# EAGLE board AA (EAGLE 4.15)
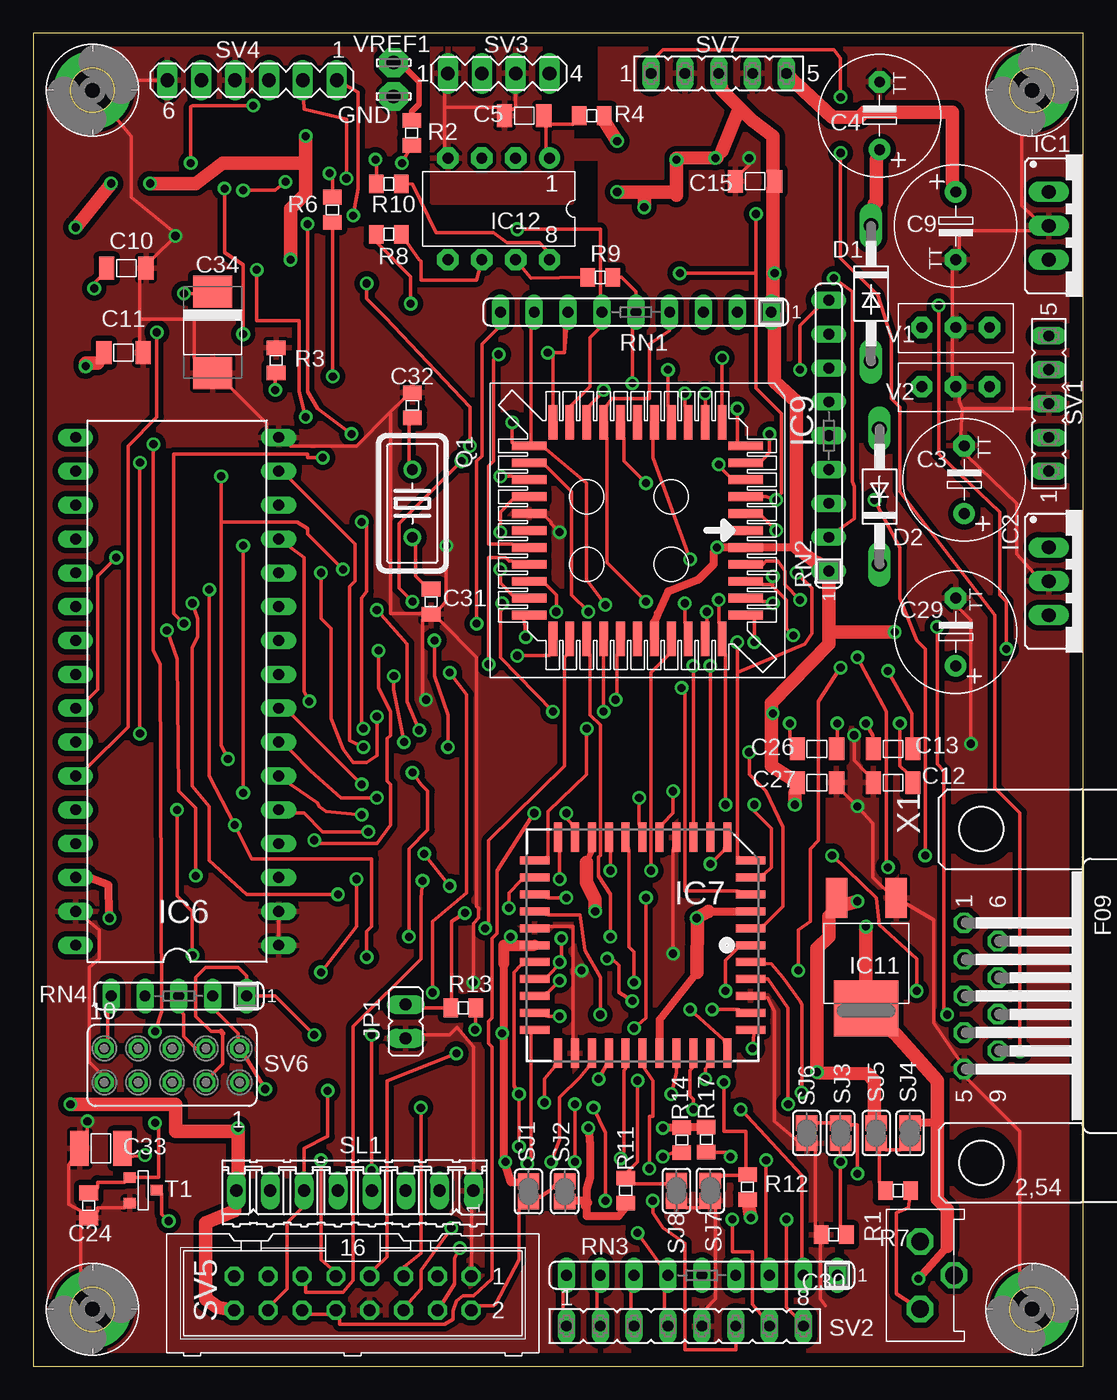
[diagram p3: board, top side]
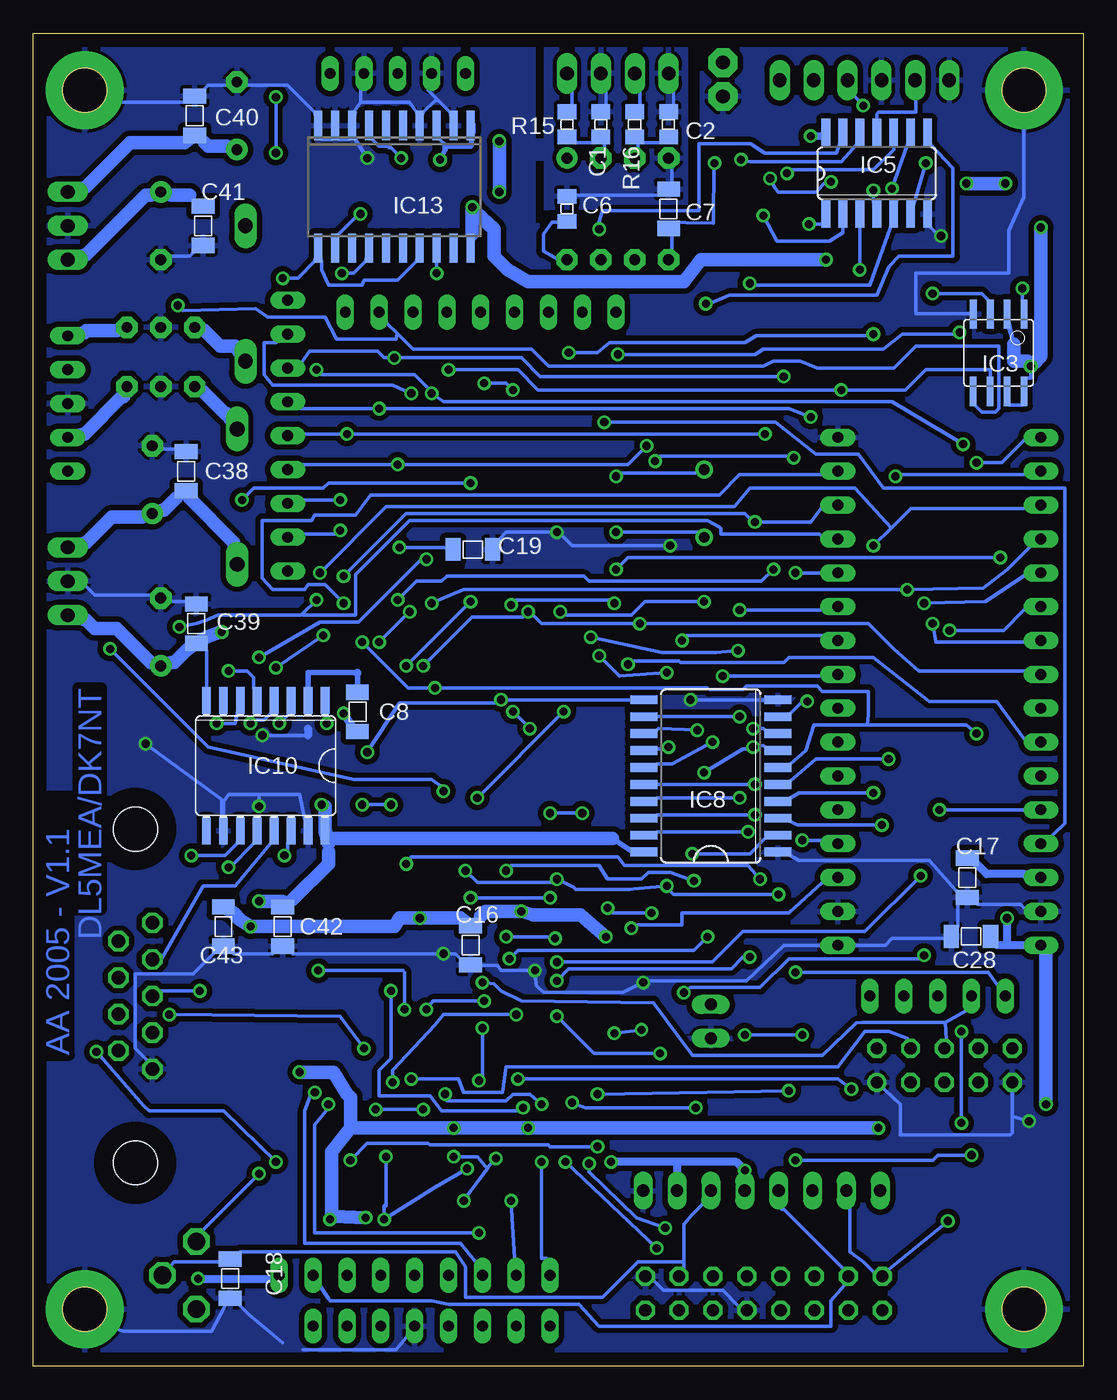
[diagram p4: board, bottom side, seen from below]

Size 78.77 x 100 mm. Coordinates in mm from the lower left corner, seen from the top.
Outline: 0,0 78.77,0 78.77,100 0,100 0,0
Copper layers (1*16): Top 0.035mm / dielectric 1.5mm / Bottom 0.035mm
Design rules "default": minimum track width 10mil, minimum drill 24mil, track to track 8mil, track to pad 8mil, pad to pad 8mil, via to via 8mil, smd to smd 8mil, copper to edge 40mil, drill to drill 8mil, minimum pad ring 10mil, minimum via ring 8mil, stop-mask expansion 4mil, vias tented up to drill 0mil, thermal gap 10mil

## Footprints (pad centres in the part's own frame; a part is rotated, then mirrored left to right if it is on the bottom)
0805 = smd 1.092 x 1.397: 1 -0.94,0; 2 0.94,0
TT5D9 = drill 0.813 pad 1.6 round: + 2.54,0 | drill 0.813 pad 1.6 octagon: - -2.54,0
C1206 = smd 1.143 x 1.702: 1 -1.473,0; 2 1.473,0
1210 = smd 1.397 x 2.591: 1 -1.6,0; 2 1.6,0
CT7243 = smd 2.388 x 2.896: 1 -3.048,0; 2 3.048,0
DO41-10 = drill 1.118 long: A 5.08,0; C -5.08,0
LSP10 = drill 1.016 pad 2.159 octagon: MP 0,0
78XXS = drill 1.016 long: GND 0,-2.54; IN -2.54,-2.54; OUT 2.54,-2.54
SOP-08 = smd 0.5 x 2.2: 1 -1.905,-2.9; 2 -0.645,-2.9; 3 0.625,-2.9; 4 1.895,-2.9; 5 1.905,2.9; 6 0.635,2.9; 7 -0.635,2.9; 8 -1.905,2.9
SO14 = smd 0.66 x 2.032: 1 -3.81,-3.073; 2 -2.54,-3.073; 3 -1.27,-3.073; 4 0,-3.073; 5 1.27,-3.073; 6 2.54,-3.073; 7 3.81,-3.073; 8 3.81,3.073; 9 2.54,3.073; 10 1.27,3.073; 11 0,3.073; 12 -1.27,3.073; 13 -2.54,3.073; 14 -3.81,3.073
DIL32 = drill 0.813 long: 1 -19.05,-7.62; 2 -16.51,-7.62; 3 -13.97,-7.62; 4 -11.43,-7.62; 5 -8.89,-7.62; 6 -6.35,-7.62; 7 -3.81,-7.62; 8 -1.27,-7.62; 9 1.27,-7.62; 10 3.81,-7.62; 11 6.35,-7.62; 12 8.89,-7.62; 13 11.43,-7.62; 14 13.97,-7.62; 15 16.51,-7.62; 16 19.05,-7.62; 17 19.05,7.62; 18 16.51,7.62; 19 13.97,7.62; 20 11.43,7.62; 21 8.89,7.62; 22 6.35,7.62; 23 3.81,7.62; 24 1.27,7.62; 25 -1.27,7.62; 26 -3.81,7.62; 27 -6.35,7.62; 28 -8.89,7.62; 29 -11.43,7.62; 30 -13.97,7.62; 31 -16.51,7.62; 32 -19.05,7.62
PLCC44 = smd 0.6 x 2.2: 1 0,8.1; 2 -1.27,8.1; 3 -2.54,8.1; 4 -3.81,8.1; 5 -5.08,8.1; 6 -6.35,8.1; 18 -6.35,-8.1; 19 -5.08,-8.1; 20 -3.81,-8.1; 21 -2.54,-8.1; 22 -1.27,-8.1; 23 0,-8.1; 24 1.27,-8.1; 25 2.54,-8.1; 26 3.81,-8.1; 27 5.08,-8.1; 28 6.35,-8.1; 40 6.35,8.1; 41 5.08,8.1; 42 3.81,8.1; 43 2.54,8.1; 44 1.27,8.1 | smd 2.2 x 0.6: 7 -8.1,6.35; 8 -8.1,5.08; 9 -8.1,3.81; 10 -8.1,2.54; 11 -8.1,1.27; 12 -8.1,0; 13 -8.1,-1.27; 14 -8.1,-2.54; 15 -8.1,-3.81; 16 -8.1,-5.08; 17 -8.1,-6.35; 29 8.1,-6.35; 30 8.1,-5.08; 31 8.1,-3.81; 32 8.1,-2.54; 33 8.1,-1.27; 34 8.1,0; 35 8.1,1.27; 36 8.1,2.54; 37 8.1,3.81; 38 8.1,5.08; 39 8.1,6.35
SO20W = smd 0.66 x 2.032: 1 -5.715,-5.029; 2 -4.445,-5.029; 3 -3.175,-5.029; 4 -1.905,-5.029; 5 -0.635,-5.029; 6 0.635,-5.029; 7 1.905,-5.029; 8 3.175,-5.029; 9 4.445,-5.029; 10 5.715,-5.029; 11 5.715,5.029; 12 4.445,5.029; 13 3.175,5.029; 14 1.905,5.029; 15 0.635,5.029; 16 -0.635,5.029; 17 -1.905,5.029; 18 -3.175,5.029; 19 -4.445,5.029; 20 -5.715,5.029
PLCC44SO = smd 0.66 x 2.591: 1 0,8.128; 2 -1.27,8.128; 3 -2.54,8.128; 4 -3.81,8.128; 5 -5.08,8.128; 6 -6.35,8.128; 18 -6.35,-8.128; 19 -5.08,-8.128; 20 -3.81,-8.128; 21 -2.54,-8.128; 22 -1.27,-8.128; 23 0,-8.128; 24 1.27,-8.128; 25 2.54,-8.128; 26 3.81,-8.128; 27 5.08,-8.128; 28 6.35,-8.128; 40 6.35,8.128; 41 5.08,8.128; 42 3.81,8.128; 43 2.54,8.128; 44 1.27,8.128 | smd 2.591 x 0.66: 7 -8.128,6.35; 8 -8.128,5.08; 9 -8.128,3.81; 10 -8.128,2.54; 11 -8.128,1.27; 12 -8.128,0; 13 -8.128,-1.27; 14 -8.128,-2.54; 15 -8.128,-3.81; 16 -8.128,-5.08; 17 -8.128,-6.35; 29 8.128,-6.35; 30 8.128,-5.08; 31 8.128,-3.81; 32 8.128,-2.54; 33 8.128,-1.27; 34 8.128,0; 35 8.128,1.27; 36 8.128,2.54; 37 8.128,3.81; 38 8.128,5.08; 39 8.128,6.35
SO16L = smd 0.66 x 2.032: 1 -4.445,-4.902; 2 -3.175,-4.902; 3 -1.905,-4.902; 4 -0.635,-4.902; 5 0.635,-4.902; 6 1.905,-4.902; 7 3.175,-4.902; 8 4.445,-4.902; 9 4.445,4.902; 10 3.175,4.902; 11 1.905,4.902; 12 0.635,4.902; 13 -0.635,4.902; 14 -1.905,4.902; 15 -3.175,4.902; 16 -4.445,4.902
DPAK = smd 1.6 x 2.997: 1 -3.531,-3.658; 3 0.94,-3.658 | smd 4.826 x 4.191: 4 -1.27,4.623
DIL08 = drill 0.813 pad 1.6 round: 1 -6.35,-2.54 | drill 0.813 pad 1.6 octagon: 2 -3.81,-2.54; 3 -1.27,-2.54; 4 1.27,-2.54; 5 1.27,5.08; 6 -1.27,5.08; 7 -3.81,5.08; 8 -6.35,5.08
SO20W' = smd 0.6 x 2.2: 1 -5.715,-4.6; 2 -4.445,-4.6; 3 -3.175,-4.6; 4 -1.905,-4.6; 5 -0.635,-4.6; 6 0.635,-4.6; 7 1.905,-4.6; 8 3.175,-4.6; 9 4.445,-4.6; 10 5.715,-4.6; 11 5.715,4.6; 12 4.445,4.6; 13 3.175,4.6; 14 1.905,4.6; 15 0.635,4.6; 16 -0.635,4.6; 17 -1.905,4.6; 18 -3.175,4.6; 19 -4.445,4.6; 20 -5.715,4.6
JP1 = drill 0.914 long: 1 0,-1.27; 2 0,1.27
BO3,3-PS = drill 3.302 pad 5.842 round: B3,3 0,0
HC18U-V = drill 0.813 round: 1 -2.54,0; 2 2.54,0
ECP10P = drill 1.321 octagon: 1 -2.54,0; 2 0,2.54; 3 2.54,0
SIL9 = drill 0.813 long: 1 -10.16,0; 2 -7.62,0; 3 -5.08,0; 4 -2.54,0; 5 0,0; 6 2.54,0; 7 5.08,0; 8 7.62,0; 9 10.16,0
SIL5 = drill 0.813 long: 1 -5.08,0; 2 -2.54,0; 3 0,0; 4 2.54,0; 5 5.08,0
SJ = smd 1.168 x 1.6: 1 -0.762,0; 2 0.762,0
08P = drill 0.914 long: 1 -8.89,0; 2 -6.35,0; 3 -3.81,0; 4 -1.27,0; 5 1.27,0; 6 3.81,0; 7 6.35,0; 8 8.89,0
FE05-1 = drill 0.813 long: 1 -5.08,0; 2 -2.54,0; 3 0,0; 4 2.54,0; 5 5.08,0
FE08 = drill 0.813 long: 1 -8.89,0; 2 -6.35,0; 3 -3.81,0; 4 -1.27,0; 5 1.27,0; 6 3.81,0; 7 6.35,0; 8 8.89,0
MA04-1 = drill 1.016 long: 1 -3.81,0; 2 -1.27,0; 3 1.27,0; 4 3.81,0
MA06-1 = drill 1.016 long: 1 -6.35,0; 2 -3.81,0; 3 -1.27,0; 4 1.27,0; 5 3.81,0; 6 6.35,0
ML16 = drill 0.914 octagon: 1 -8.89,-1.27; 2 -8.89,1.27; 3 -6.35,-1.27; 4 -6.35,1.27; 5 -3.81,-1.27; 6 -3.81,1.27; 7 -1.27,-1.27; 8 -1.27,1.27; 9 1.27,-1.27; 10 1.27,1.27; 11 3.81,-1.27; 12 3.81,1.27; 13 6.35,-1.27; 14 6.35,1.27; 15 8.89,-1.27; 16 8.89,1.27
FE05-2 = drill 0.914 round: 1 -5.08,1.27 | drill 0.914 octagon: 2 -5.08,-1.27; 3 -2.54,1.27; 4 -2.54,-1.27; 5 0,1.27; 6 0,-1.27; 7 2.54,1.27; 8 2.54,-1.27; 9 5.08,1.27; 10 5.08,-1.27
SOT-23 = smd 0.787 x 0.889: 1 -0.94,1.016; 2 0.991,1.016; 3 0.025,-1.016
EMV1 = drill 0.813 pad 1.6 octagon: 1 -2.54,0; 2 0,0; 3 2.54,0
F09H = drill 1.016 octagon: 1 -5.486,-1.27; 2 -2.743,-1.27; 3 0,-1.27; 4 2.743,-1.27; 5 5.486,-1.27; 6 -4.115,1.27; 7 -1.372,1.27; 8 1.372,1.27; 9 4.115,1.27 | hole 3.302: -12.522,0; 12.522,0

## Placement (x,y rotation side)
C1  100pF  [0805]  36.19,93.18 90 bottom
C2  100pF  [0805]  31.11,93.18 270 bottom
C3  47/25V  [TT5D9]  69.84,66.51 270 top
C4  47/25V  [TT5D9]  63.5,93.81 270 top
C5  100nF  [C1206]  36.83,93.81 180 top
C6  100pF  [0805]  38.73,86.83 90 bottom
C7  100nF  [C1206]  31.11,86.83 270 bottom
C8  1uF  [C1206]  54.45,49.1 270 bottom
C9  47/16V  [TT5D9]  69.21,85.56 90 top
C10  100nF  [C1206]  6.98,82.39 180 top
C11  100nF  [C1206]  6.77,76.04 0 top
C12  1uF  [C1206]  64.51,43.78 180 top
C13  1uF  [C1206]  64.51,46.32 0 top
C15  100nF  [C1206]  54.16,88.89 180 top
C16  100nF  [C1206]  45.97,31.58 270 bottom
C17  100nF  [C1206]  8.69,36.64 270 bottom
C18  100nF  [C1206]  64,6.57 270 bottom
C19  100nF  [C1206]  45.8,61.28 0 bottom
C24  1nF  [0805]  4.16,12.07 270 top
C26  1uF  [C1206]  58.8,46.32 0 top
C27  1uF  [C1206]  58.8,43.78 0 top
C28  100nF  [C1206]  8.42,32.24 180 bottom
C29  47/16V  [TT5D9]  69.21,55.08 270 top
C30  10nF  [0805]  60.07,9.87 180 top
C31  12pF  [0805]  29.84,57.37 270 top
C32  12pF  [0805]  28.44,72.1 90 top
C33  4.7uF/10V  [1210]  5.08,16.34 180 top
C34  10uF/16V  [CT7243]  13.46,77.56 270 top
C38  100nF  [C1206]  67.3,67.14 270 bottom
C39  100nF  [C1206]  66.54,55.71 270 bottom
C40  100nF  [C1206]  66.67,93.81 270 bottom
C41  100nF  [C1206]  66.03,85.56 90 bottom
C42  100nF  [C1206]  60.07,32.98 90 bottom
C43  100nF  [C1206]  64.51,32.98 90 bottom
D1  1N4004  [DO41-10]  62.86,80.48 270 top
D2  1N4004  [DO41-10]  63.5,65.24 90 top
GND  LSP10  [LSP10]  27.03,95.27 0 top
IC1  78M12  [78XXS]  78.73,85.56 270 top
IC2  78M05  [78XXS]  78.73,58.89 270 top
IC3  TL7705SO  [SOP-08]  6.34,76.03 180 bottom
IC5  74HC04D  [SO14]  15.49,89.5 0 bottom
IC6  8K*8/128K*8 SRAM  [DIL32]  10.79,50.63 90 top
IC7  XCR3064PLCC44  [PLCC44]  45.72,31.58 270 top
IC8  74HCT573D  [SO20W]  27.93,44.28 90 bottom
IC9  89C51RD2  [PLCC44SO]  45.33,62.7 270 top
IC10  MAX232AECWE  [SO16L]  61.34,45.05 180 bottom
IC11  MC33269  [DPAK]  61.21,31.46 180 top
IC12  MAX157  [DIL08]  32.38,88.1 180 top
IC13  FM24C256  [SO20W']  51.68,88.48 180 bottom
JP1  [JP1]  27.93,25.87 0 top
PAD1  BO3,3PS  [BO3,3-PS]  4.44,95.72 0 top
PAD2  BO3,3PS  [BO3,3-PS]  74.92,95.72 0 top
PAD3  BO3,3PS  [BO3,3-PS]  74.92,4.28 0 top
PAD4  BO3,3PS  [BO3,3-PS]  4.44,4.28 0 top
Q1  11.052MHz  [HC18U-V]  28.44,64.73 270 top
R1  10K  [ECP10P]  66.54,6.82 270 top
R2  47  [0805]  28.39,92.53 90 top
R3  4.7K  [0805]  18.22,75.46 90 top
R4  10  [0805]  41.91,93.81 0 top
R6  10  [0805]  22.44,86.77 90 top
R7  10K  [0805]  64.89,13.17 180 top
R8  47  [0805]  26.66,84.92 180 top
R9  47  [0805]  42.54,81.69 0 top
R10  47  [0805]  26.66,88.7 180 top
R11  4.7K  [0805]  44.45,13.17 270 top
R12  4.7K  [0805]  53.59,13.42 270 top
R13  4.7K  [0805]  32.25,26.89 0 top
R14  4.7K  [0805]  48.66,16.96 270 top
R15  22  [0805]  38.73,93.18 270 bottom
R16  22  [0805]  33.65,93.18 270 bottom
R17  4.7K  [0805]  50.5,17 270 top
RN1  4.7K  [SIL9]  45.21,79.08 180 top
RN2  4.7K  [SIL9]  59.69,69.81 90 top
RN3  4.7K  [SIL9]  50.16,6.82 180 top
RN4  4,7K  [SIL5]  10.92,27.77 180 top
SJ1  [SJ]  37.16,13.11 90 top
SJ2  [SJ]  39.88,13.11 90 top
SJ3  [SJ]  60.57,17.49 90 top
SJ4  [SJ]  65.78,17.49 90 top
SJ5  [SJ]  63.24,17.49 90 top
SJ6  [SJ]  58.03,17.49 90 top
SJ7  [SJ]  50.8,13.17 270 top
SJ8  [SJ]  48.26,13.17 270 top
SL1  [08P]  24.12,13.17 180 top
SV1  [FE05-1]  76.19,72.22 90 top
SV2  [FE08]  48.89,3.01 0 top
SV3  [MA04-1]  34.92,96.99 0 top
SV4  [MA06-1]  16.41,96.48 180 top
SV5  [ML16]  23.97,5.47 180 top
SV6  Pfosten2*5  [FE05-2]  10.41,22.57 180 top
SV7  [FE05-1]  51.43,96.99 0 top
T1  FDN335N  [SOT-23]  8.25,13.17 90 top
V1  DSS306  [EMV1]  69.21,77.94 180 top
V2  DSS306  [EMV1]  69.21,73.5 180 top
VREF1  LSP10  [LSP10]  27.03,97.8 0 top
X1  [F09H]  71.11,27.77 270 top

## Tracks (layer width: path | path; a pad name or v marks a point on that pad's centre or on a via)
+3V  (via drill 0.6, 0.61)
  Top 0.254: 35.3,15.33 35.36,15.27 v35.43,15.33 | 46.98,24.73 IC7.35 | 41.91,38.7 IC7.15 | v49.78,33.62 50.41,34.12 49.84,33.68 | 35.81,31.84 v35.81,32.22 | 13.06,21.53 14.22,22.7 14.22,24.98 | 14.09,25.11 13.33,25.11 12.19,26.25 12.19,29.17 12.95,29.93 15.36,29.93 16,29.3 RN4.1 18.16,27.77 v21.08,24.85 | R13.2 33.19,25.29 v33.14,25.23 | 35.3,24.73 v35.17,24.98 | v25.39,24.85 v25.39,14.69
  Top 0.406: 41.52,37.81 41.91,38.7 | 12.82,20.92 13.08,21.17 SV6.3 13.06,21.3 13.06,21.53 | 14.22,24.98 14.09,25.11
  Top 0.61: 35.36,15.27 35.81,13.81 SJ1.2 | 35.3,15.33 35.3,24.73 35.3,30.19 | 68.57,8.98 v66.42,6.57 | 67.81,18.25 SJ4.2 | 46.98,24.73 46.98,26 49.78,29.55 | 50.67,34.12 IC7.3
  Top 0.813: 35.3,30.19 35.3,31.58 35.94,31.58 | 35.94,31.58 35.81,31.84 | 35.94,31.58 IC7.23
  Top 1.016: 68.57,8.98 68.57,11.77 67.81,12.54 67.81,18.25 67.81,21.42 64.77,24.85 IC11.4 v62.48,32.98 | 50.67,34.12 49.84,33.68 49.78,29.55 | v42.16,34.12 42.16,35.01 41.52,36.28 41.52,37.81
  Bottom 0.254: 45.21,33.74 45.21,33.49 C16.1 | v35.17,24.98 v33.14,25.23 | v21.08,24.85 v25.39,24.85
  Bottom 0.61: 30.47,15.33 26.03,15.33 v25.39,14.69 SL1.4 | 30.47,15.33 v35.43,15.33 | 30.47,15.33 SL1.2 | v66.42,6.57 60.57,6.57 RN3.1
  Bottom 1.016: C16.1 46.73,33.62 v49.78,33.62 51.3,33.62 51.68,32.98 v62.48,32.98 63.24,33.49 63.75,34 C43.2 | 45.21,33.74 44.83,34.12 v42.16,34.12 41.27,33.87 37.71,33.87 v35.81,32.22
+5V  (via drill 0.6, 0.61)
  Top 0.254: 3.93,75.27 v3.93,75.02 3.68,74.64 | 4.82,75.27 C11.1 | v5.71,33.62 5.71,33.87 | 41.52,11.27 41.39,12.02 | 44.45,11.9 R11.2 | 10.66,17.61 13.97,17.36 15.62,17.61 | SL1.8 15.22,13.27 15.24,17.61 | 59.69,33.74 IC11.3 60.96,34.63 | v51.3,61.43 51.05,61.05 | 58.8,60.29 59.05,60.03 | 42.92,93.31 R4.2 | 55.49,88.35 C15.1 55.49,89.62 | RN1.1 55.49,79.34 | 55.49,82.26 v55.62,82 | 53.08,94.32 52.95,94.32 | 57.15,43.02 C27.1 | 51.68,91.15 51.29,90.68 49.38,90.53 49.4,90.51 49.53,90.64 v51.18,90.64 | SV2.8 57.78,3.14 56.51,4.41 v56.51,11.01 | v47.24,17.87 47.37,17.9 | R14.1 48.76,17.9 48.76,17.94
  Top 0.406: v48.26,90.51 48.38,90.51 | 47.87,88.1 47.93,88.1 47.93,87.85 48.26,87.85
  Top 0.61: 5.71,33.87 5.65,36.09 4.19,36.66 IC6.30 | 41.52,12.41 41.52,11.27 43.94,11.27 44.45,11.9 | 41.52,12.41 40.76,12.41 SJ2.1 | v51.3,61.43 IC9.44 57.27,61.43 | 51.05,61.05 51.05,60.16 49.91,59.02 47.62,58.13 46.86,56.48 46.6,55.84 IC9.35 | v41.65,17.87 41.78,16.6 41.78,14.19 41.52,13.3 41.52,12.41 | 41.39,12.02 41.65,12.28 41.52,12.41 | 55.37,46.19 55.24,46.19 v55.49,48.98 | 47.37,17.9 R14.1 | 48.76,17.94 R17.1
  Top 1.016: 3.93,75.27 4.82,75.27 | SL1.8 15.11,11.65 12.95,10.76 12.95,5.04 13.84,4.41 SV5.16 15.11,4.28 | 15.24,17.61 10.66,17.61 10.66,19.65 v2.79,19.65 | 59.69,33.74 59.69,32.22 58.8,31.33 v58.8,22.06 58.86,22 62.61,21.93 63.11,21.42 63.11,18.76 SJ5.2 | 60.96,34.63 v61.84,34.89 | C27.1 55.37,45.05 55.37,46.19 55.37,49.75 59.69,54.19 59.69,55.08 | 59.05,60.03 57.27,61.43 57.27,72.35 55.62,73.88 55.62,78.83 RN1.1 | 58.8,60.29 RN2.1 59.69,55.08 | 59.69,55.08 v64.64,55.08 | 47.87,88.1 45.84,88.1 | 45.84,88.1 v43.81,88.1 | v43.81,91.91 42.92,93.31 | 55.49,79.34 55.49,82.26 55.49,88.35 | 55.49,89.62 55.49,92.29 53.91,93.5 53.08,94.32 51.68,95.72 SV7.3 | 52.95,94.32 51.68,91.15 | 48.26,87.85 v48.26,90.51 48.26,90.64 51.29,90.68 | v19.3,83.02 19.3,86.83 20.44,87.97 20.44,90.26 | 20.44,90.26 v20.44,92.29 | v57.15,42.13 57.15,43.02 | v5.84,88.73 v3.17,85.43 | v8.76,88.73 12.19,88.73 14.22,90.26 20.44,90.26 | 45.84,88.1 v45.84,86.96 | v53.84,11.14 R12.2 | 15.22,13.27 15.34,13.27 15.36,13.3 v15.36,17.87
  Bottom 0.254: IC3.7 5.58,72.1 4.57,72.1 IC3.8 4.31,74.13 3.93,74.13 v3.93,75.02 4.19,75.4 4.06,75.27 3.68,75.27 | 59.3,35.01 C42.2 60.07,34.89 | 56.64,38.57 56.64,39.2 56.64,39.46 56.76,39.59 | 68.45,52.79 C29.+ | IC10.8 65.78,53.68 C39.2 | v51.3,61.43 47.75,61.43 C19.1 | v64.64,55.08 64.77,55.08 | v55.62,82 54.73,82 53.84,82.89 IC13.14 | 45.72,92.55 45.72,93.18 IC13.1 | 19.43,83.02 v19.3,83.02 | 45.84,84.92 IC13.20 | IC13.1 45.84,92.16 45.84,91.53 45.97,91.53 | 47.81,91.59 47.75,91.53 45.97,91.53 | 47.81,91.59 48.26,92.04 IC13.3 | 52.83,91.53 53.34,92.04 IC13.7 53.59,92.29 52.83,91.53 | 47.87,91.53 47.81,91.59 | 45.97,91.53 IC13.1 | 52.83,91.53 52.19,91.53 52.07,91.4 51.94,91.4 v51.18,90.64 | 19.58,92.32 IC5.14 | 56.26,11.26 56.26,11.27 | 56.26,11.25 56.26,11.26 | 56.26,11.26 v56.51,11.01 | 5.2,76.67 IC3.2 5.7,78.33 5.71,78.32 5.71,78.19 5.2,76.67
  Bottom 0.406: 35.3,39.59 33.78,38.57 IC8.20 | v48.26,90.51 47.87,91.28 47.87,91.53 45.97,91.53 | v45.84,86.96 45.97,86.96 45.59,86.58
  Bottom 0.61: 5.71,31.58 6.47,31.58 C28.1 | IC6.32 5.71,31.58 | C17.1 7.87,37.55 7.23,36.92 4.44,36.92 IC6.30 | 5.71,31.58 v5.71,33.62 | v20.44,92.29 19.58,92.32 | C8.2 54.45,47.36 v55.49,48.98
  Bottom 1.016: v2.79,19.65 2.79,31.08 IC6.32 | 59.3,35.01 56.64,37.68 56.64,38.57 | 56.64,39.2 IC10.16 56.89,42 v57.15,42.13 | 56.76,39.59 35.3,39.59 | v61.84,34.89 60.07,34.89 | 68.45,52.79 68.19,52.79 67.3,53.68 C39.2 65.78,54.7 64.77,55.08 | IC2.OUT 74.8,55.97 74.16,55.33 72.51,55.33 69.97,52.79 C29.+ | v43.81,88.1 v43.81,91.91 | 19.43,83.02 28.7,83.02 29.97,81.37 41.65,81.37 43.18,82.26 44.19,83.27 44.19,85.31 45.59,86.58 | 54.99,17.87 56.38,16.09 56.38,11.27 56.26,11.25 v53.84,11.14 | 54.99,17.87 54.99,20.15 55.24,20.41 56.26,22.06 v58.8,22.06 | 5.2,76.67 5.2,75.4 4.19,75.4 | 3.68,75.27 3.17,75.78 v3.17,85.43 | v8.76,88.73 v5.84,88.73 | v45.84,86.96 45.84,84.92 | 54.99,17.87 v47.24,17.87 v41.65,17.87 v15.36,17.87
+12V
  Top 1.016: C9.+ 68.96,88.86 68.96,94.07 62.35,94.07 61.97,93.69 59.94,93.69 57.27,96.23 SV7.5
  Bottom 0.254: 67.05,87.85 66.8,87.59 C41.2 | C9.+ 69.97,87.85
  Bottom 1.016: 67.05,87.85 68.45,87.85 C9.+ | 69.97,87.85 70.35,87.85 74.8,83.4 IC1.OUT
-V  (via drill 0.61)
  Top 0.254: C30.1 60.57,10.5 v60.57,15.33 SJ3.1 | 60.57,91.15 v60.57,91.02 60.57,83.15 63.37,80.35 64.38,77.18 64.38,72.61 65.02,71.97 65.02,65.62 72.13,56.35 72.13,43.4 74.04,41.49 v74.04,23.58 | v60.57,95.21 60.57,98.13 60.07,98.77 47.24,98.77 46.35,97.88 SV7.1
  Bottom 0.254: v60.57,91.02 v60.57,95.21 | v74.04,23.58 70.48,19.52 70.1,19.14 64.51,19.14 v60.57,15.33
A00  (via drill 0.61)
  Top 0.254: v25.78,48.73 25.78,45.81 25.01,45.3 24,45.3 23.24,46.32 22.35,48.6 22.35,55.33 21.58,56.1 v21.58,59.52
  Bottom 0.254: v21.58,59.52 21.46,59.4 21.2,59.52 IC6.12 18.28,59.65 | v25.78,48.73 IC8.12
A01  (via drill 0.61)
  Top 0.254: v28.95,47.71 28.06,49.87 28.06,54.19 v25.78,56.73
  Bottom 0.254: v28.95,47.71 31.87,47.84 32,47.71 IC8.13 | v25.78,56.73 19.68,56.73 IC6.11
A02  (via drill 0.61)
  Top 0.254: v31.11,46.44 31.11,48.86 30.09,51.78 v30.09,54.45
  Bottom 0.254: v31.11,46.44 31.24,46.32 31.87,46.32 IC8.14 | v30.09,54.45 29.71,54.83 19.55,54.83 IC6.10
A03  (via drill 0.61)
  Top 0.254: v27.81,46.82 27.05,50.76 v27.05,51.78
  Bottom 0.254: v27.81,46.82 30.86,45.17 32,45.17 IC8.15 | v27.05,51.78 19.68,51.78 IC6.9
A04  (via drill 0.61)
  Top 0.254: v24.63,43.65 19.43,48.86 IC6.8
  Bottom 0.254: v24.63,43.65 IC8.16
A05  (via drill 0.61)
  Top 0.254: v25.78,42.63 23.11,42.63 20.82,44.67 19.3,46.19 IC6.7
  Bottom 0.254: v25.78,42.63 32,42.63 IC8.17
A06  (via drill 0.61)
  Top 0.254: v24.63,41.36 21.97,41.62 21.46,42 21.33,42.25 19.3,43.65 IC6.6
  Bottom 0.254: v24.63,41.36 32,41.36 IC8.18
A07  (via drill 0.61)
  Top 0.254: v25.14,40.09 21.71,40.09 20.31,41.49 19.68,41.49 IC6.5
  Bottom 0.254: v25.14,40.09 32,40.09 IC8.19
A08  (via drill 0.61)
  Top 0.254: v34.92,75.91 34.54,75.53 34.54,67.91 34.16,67.53 34.16,61.68 35.94,61.68 IC9.24 | v9.27,77.56 9.27,71.21 7.11,69.05 7.11,47.97 4.06,44.92 IC6.27
  Bottom 0.254: v34.92,75.91 24.63,75.91 24,76.29 14.98,76.29 13.58,77.43 9.39,77.43 v9.27,77.56
A09  (via drill 0.61)
  Top 0.254: v34.16,52.67 34.16,60.67 35.43,60.67 35.68,60.41 35.94,60.41 IC9.25
  Bottom 0.254: v34.16,52.67 33.9,52.92 30.35,52.92 30.22,52.79 22.47,52.79 22.09,53.17 15.74,53.17 11.55,49.87 6.47,49.87 4.44,47.08 IC6.26
A10  (via drill 0.61)
  Top 0.254: v39.24,56.6 39.24,57.87 38.48,58.64 IC9.26 | v28.44,57.37 27.43,58.38 27.43,63.21 v32.13,67.91 | v21.71,68.16 20.57,68.16 20.57,68.41 10.54,68.41 10.54,56.48 v11.3,55.71
  Bottom 0.254: v39.24,56.6 38.98,56.35 33.9,56.35 32.89,57.37 v28.44,57.37 | v32.13,67.91 31.74,68.29 21.84,68.29 v21.71,68.16 | v11.3,55.71 11.04,54.32 4.44,54.32 IC6.23
A11  (via drill 0.61)
  Top 0.254: v35.05,59.78 35.05,58.76 35.94,57.87 IC9.27 | v6.22,60.67 4.82,59.27 4.82,50.76 4.06,50 IC6.25
  Bottom 0.254: v35.05,59.78 34.16,60.67 v6.22,60.67
A12  (via drill 0.61)
  Top 0.254: v36.95,54.7 36.83,56.1 36.7,56.35 IC9.28 | v25.9,53.68 25.9,50.89 26.79,49.11 26.79,47.33 26.54,47.08 26.54,43.9 26.79,43.65 26.79,40.6 25.78,39.2 21.08,39.2 v21.08,39.46
  Bottom 0.254: v36.95,54.7 31.62,53.56 27.55,53.56 v25.9,53.68 | v21.08,39.46 19.68,39.46 IC6.4
A13  (via drill 0.61)
  Top 0.254: v36.32,53.3 38.73,53.3 IC9.29 | v31.24,52.03 32.51,50.38 32.51,35.52 29.97,33.36 v29.97,28.03 | v11.93,30.82 11.93,34.12 10.79,35.27 v10.79,41.74
  Bottom 0.254: v36.32,53.3 34.79,51.78 v31.24,52.03 | v29.97,28.03 29.46,28.41 24.25,28.41 22.09,30.57 11.93,30.57 v11.93,30.82 | v10.79,41.74 IC6.28
A14  (via drill 0.61)
  Top 0.254: v33.9,32.85 34.16,33.36 34.16,39.46 39.87,45.05 39.87,53.17 40,53.3 IC9.30
  Bottom 0.254: v33.9,32.85 33.65,33.11 30.09,33.11 30.09,34 22.09,34 19.17,36.66 IC6.3
AD0  (via drill 0.61)
  Top 0.254: v20.7,49.87 20.31,50.63 20.31,60.67 19.3,61.43 IC6.13 | v53.97,23.84 54.1,25.23 IC7.40 | v67.81,55.46 67.81,45.17 68.32,44.67 68.32,26.38 v68.57,26.38 | v57.53,57.49 56.38,58.64 56.38,59.65 55.88,60.41 54.99,60.41 54.73,60.16 IC9.43
  Bottom 0.254: v20.7,49.87 20.95,50 21.97,48.98 IC8.9 | v53.97,23.84 55.75,26.25 v68.57,26.38 | v67.81,55.46 66.54,55.71 65.78,55.97 64.89,56.35 58.67,56.35 58.61,56.41 | 58.61,56.41 v57.53,57.49 | IC6.13 19.68,62.32 19.81,62.45 27.17,62.45 27.17,62.83 27.3,62.95 28.19,63.46 50.54,63.46 54.61,59.4 54.61,56.35 58.54,56.35 58.61,56.41
AD1  (via drill 0.61)
  Top 0.254: v24.76,47.84 24.76,48.22 24.63,48.35 24.63,57.62 25.01,58.13 25.01,63.34 v24.63,63.34 | v50.92,26.76 52.83,26.76 IC7.41 | v57.4,29.68 57.4,32.73 58.29,33.36 58.29,38.82 58.92,39.46 58.92,49.87 v60.57,52.41 | v57.02,54.83 56.51,55.33 56.51,57.49 55.43,58.57 | 55.43,58.57 55.37,58.64 54.73,58.64 IC9.42 | v55.49,59.27 55.49,58.64 55.43,58.57
  Bottom 0.254: v24.76,47.84 24,47.84 23.87,47.71 IC8.8 | IC6.14 19.68,64.35 20.44,63.34 v24.63,63.34 25.01,63.59 25.39,63.97 50.8,63.97 v55.49,59.27 | v57.4,29.68 51.05,29.68 50.92,29.55 v50.92,26.76 | v57.02,54.83 v60.57,52.41
AD2  (via drill 0.61)
  Top 0.254: v24.76,46.44 23.74,46.95 23.74,58.51 24.12,58.89 24.12,61.68 19.3,66.51 IC6.15 | v49.27,26.76 51.81,24.47 IC7.39 | v44.95,27.39 43.94,28.03 43.94,30.06 43.43,30.57 v43.05,30.57 | v28.19,32.22 28.19,38.82 29.59,40.22 29.59,43.14 29.08,43.65 v28.44,44.54 | v55.49,57.24 55.49,57.37 54.73,57.37 IC9.41
  Bottom 0.254: IC8.7 23.87,46.44 24,46.57 v24.76,46.44 25.01,46.32 25.52,46.32 v28.44,44.54 | v49.27,26.76 48.76,27.39 v44.95,27.39 | v43.05,30.57 42.41,31.2 29.2,31.2 v28.19,32.22 | v55.49,57.24 56.89,58.64 58.16,58.64 58.41,58.25 60.83,58.25 61.59,59.14 61.59,63.46 57.91,63.46 57.65,63.84 54.61,63.84 53.46,65.37 27.3,65.37 25.78,66.89 19.68,66.89 IC6.15
AD3  (via drill 0.61)
  Top 0.254: v54.1,54.32 54.1,56.1 IC9.40 | v48.64,50.89 48.89,50.63 48.89,35.65 52.83,35.65 IC7.4 | v8,47.46 v8,67.78
  Bottom 0.254: 17.27,48.09 20.19,48.09 20.82,46.19 21.97,45.17 IC8.6 | v54.1,54.32 50.67,50.89 v48.64,50.89 28.19,50.89 28.06,50.76 25.52,50.76 25.27,51.02 19.93,51.02 19.55,50.63 16.12,50.63 16.12,48.86 16.19,48.16 17.27,48.09 | v8,67.78 6.09,67.78 4.44,69.43 IC6.17 | v8,47.46 8.76,48.09 17.27,48.09
AD4  (via drill 0.61)
  Top 0.254: v54.1,42.13 54.1,41.62 55.37,40.35 55.37,37.43 54.86,36.92 IC7.5 | v51.94,42.13 51.94,53.3 IC9.39 51.43,55.84 v51.43,57.49 | v14.6,45.55 14.09,46.57 14.09,63.34 | 14.09,63.34 v14.09,66.76 | v23.24,59.78 20.57,62.45 20.57,62.83 19.81,63.34 14.09,63.34
  Bottom 0.254: v51.94,42.13 v54.1,42.13 | v14.6,45.55 20.06,45.55 21.97,43.9 IC8.5 | v14.09,66.76 13.97,66.89 4.44,66.89 IC6.18 | v51.43,57.49 50.03,58.89 48.13,58.89 47.75,59.27 37.46,59.27 37.08,58.89 24.12,58.89 v23.24,59.78
AD5  (via drill 0.61)
  Top 0.254: 52.83,52.03 v52.83,54.32 | 52.83,52.03 52.83,38.19 IC7.6 | v50.54,56.6 50.54,55.84 IC9.38 | v15.74,43.02 v15.74,61.56 | 52.83,52.03 57.91,54.19 58.41,54.95 58.41,58.38 v57.27,59.52
  Bottom 0.254: v52.83,54.32 v50.54,56.6 | v15.74,43.02 21.33,43.02 21.97,42.63 IC8.4 | 14.41,62.89 12.95,64.35 4.44,64.35 IC6.19 | v15.74,61.56 14.41,62.89 | v57.27,59.52 52.32,64.48 26.16,64.48 25.01,65.88 17.14,65.88 14.41,62.89
AD6  (via drill 0.61)
  Top 0.254: v13.2,58.25 13.2,44.28 v15.11,40.6 16.38,38.06 25.39,38.06 25.39,32.98 25.01,32.6 v25.01,30.7 | v39.49,28.92 38.6,28.03 IC7.26 | v48.89,57.24 48.89,55.84 IC9.37
  Bottom 0.254: v15.11,40.6 21.46,40.6 21.97,40.86 IC8.3 | IC6.20 4.06,61.43 5.71,59.78 7.49,58.38 v13.2,58.25 46.48,58.25 v48.89,57.24 | v39.49,28.92 38.6,29.81 26.41,29.81 25.52,30.7 v25.01,30.7
AD7  (via drill 0.61)
  Top 0.254: v31.24,36.03 v29.33,38.44 | v39.49,36.54 39.49,38.7 IC7.17 | v46.35,37.17 46.35,52.03 47.62,53.3 IC9.36 | v11.93,57.24 12.31,56.1 12.31,54.7 11.93,53.94 11.93,43.52 13.2,42 13.2,37.94 16,35.39 v22.86,35.39
  Bottom 0.254: v29.33,38.44 25.01,38.44 23.87,39.59 IC8.2 | 34.16,35.78 v31.24,36.03 31.24,35.9 30.73,35.39 v22.86,35.39 | 34.16,35.78 34.03,35.78 | 34.16,35.78 38.1,35.78 38.22,35.9 v39.49,36.54 39.87,36.28 45.46,36.28 v46.35,37.17 | v11.93,57.24 7.36,57.37 4.44,59.27 IC6.21
ADCCLK  (via drill 0.61)
  Top 0.254: v36.32,85.31 42.54,85.31 42.54,80.23 RN1.6 42.41,77.81 41.78,77.18 41.78,73.5 40.38,72.1 IC9.16
  Bottom 0.254: v36.32,85.31 36.32,85.81 36.06,86.7 28.82,86.7 28.82,88.86 28.83,91.72 24.99,91.72 23.87,91.02 18.54,91.02 18.28,91.66 IC5.13
ADCCS-  (via drill 0.61)
  Top 0.254: v15.74,77.43 15.74,82.64 14.35,83.53 v14.35,88.35 | v38.6,76.03 38.98,76.03 | 39.87,76.03 RN1.7 39.87,77.81 39.87,76.03 | 38.98,76.03 39.87,76.03 | 38.98,76.03 IC9.17
  Bottom 0.254: v14.35,88.35 13.2,91.66 IC5.9 | v15.74,77.43 16.38,77.3 24.51,77.3 25.39,76.8 35.55,76.8 36.44,76.03 v38.6,76.03
ADCDATA  (via drill 0.61)
  Top 0.254: v42.79,73.24 42.79,73.11 41.78,72.1 IC9.15 | v44.95,73.75 44.95,77.81 RN1.5 45.08,79.08 45.21,79.21 45.21,80.61 44.13,81.69 R9.2
  Bottom 0.254: v42.79,73.24 43.3,73.75 v44.95,73.75
ADR15  (via drill 0.61)
  Top 0.254: 39.55,30.25 39.62,30.31 v39.62,32.09 | 39.55,30.25 38.6,29.3 IC7.25 | v43.3,32.22 43.3,35.39 42.41,36.79 42.41,38.19 42.54,38.32 42.54,48.09 41.78,48.86 41.78,53.3 IC9.31 | v10.03,55.21 10.79,53.05 10.92,43.14 12.19,41.87 v12.19,36.79 | v39.49,30.31 39.55,30.25
  Bottom 0.254: v39.62,32.09 39.75,32.22 v43.3,32.22 | v10.03,55.21 5.96,55.21 4.44,56.73 IC6.22 | v12.19,36.79 16.38,32.6 25.52,32.6 27.81,30.31 v39.49,30.31
ALE  (via drill 0.61)
  Top 0.254: v43.68,50 43.81,50.13 43.81,53.3 IC9.33 | v53.72,46.06 53.72,44.41 54.99,43.14 56.26,40.48 56.26,34.51 54.86,33.11 IC7.2
  Bottom 0.254: IC8.11 v43.68,50 44.06,49.75 51.3,49.75 v53.72,46.06
DREHSTB  (via drill 0.6, 0.61)
  Top 0.254: v46.22,14.82 46.22,18.76 46.48,18.76 46.48,21.42 45.72,22.57 IC7.34 | 52.32,10.88 v52.45,11.01 52.45,8.6 53.97,8.6 53.97,4.66 54.61,3.9 SV2.7 | R17.2 52.32,16.06 v52.32,15.71
  Bottom 0.254: v46.22,14.82 48.64,13.42 v52.45,11.01 52.45,12.03 52.32,12.03 v52.32,15.71
DREHUD  (via drill 0.6, 0.61)
  Top 0.254: v44.06,15.58 44.32,16.09 44.32,22.19 44.45,22.31 IC7.33 | v46.48,12.41 46.48,11.52 47.24,10.38 48.89,9.23 48.89,1.23 52.7,1.23 SV2.6 | R14.2 48.13,16.02 48.13,16.09 v47.24,15.71
  Bottom 0.254: v44.06,15.58 44.45,15.2 46.22,12.79 | v46.48,12.41 46.22,12.79 | 46.22,12.79 44.7,14.82 45.46,15.71 v47.24,15.71
FRAM_SCD  (via drill 0.61)
  Top 0.254: v55.75,62.7 54.73,63.72 IC9.2 | v60.07,81.62 61.46,80.61 61.46,66.38 61.59,66 61.59,63.59 60.57,62.83 RN2.2
  Bottom 0.254: IC13.17 50.03,82.89 51.43,81.5 53.97,81.5 54.1,81.11 56.64,81.11 57.15,82.26 57.15,82.89 IC13.11 57.65,82.89 58.92,81.62 v60.07,81.62 | v55.75,62.7 56,62.45 58.41,62.45 RN2.2
FRAM_SCL  (via drill 0.61)
  Top 0.254: IC9.3 54.99,65.24 v55.75,64.99 56,65.37 56.13,65.49 56.13,71.46 54.22,73.37 54.22,82 | 54.22,82 v54.22,86.45 | 54.22,82 v48.51,82
  Bottom 0.254: v55.75,64.99 58.41,64.99 RN2.3 | 54.29,86.51 55.88,84.92 IC13.12 | 54.29,86.51 54.1,86.7 | v54.22,86.45 54.29,86.51 | v48.51,82 IC13.18
GND  (via drill 0.61)
  Top 0.254: SV4.6 7.23,96.48 PAD1.B3,3 7.36,92.29 7.36,87.72 10.41,85.18 v10.66,84.8 9.01,83.15 C10.1 8,81.62 8,78.58 | 8,78.58 8,76.8 C11.2 | v39.49,62.57 38.86,63.21 38.86,63.34 38.48,63.72 IC9.22 | 26.73,71.53 24.25,69.05 19.3,69.05 IC6.16 17.52,70.32 17.52,70.7 14.85,73.37 C34.2 12.06,75.65 12.06,78.58 8,78.58 | 26.73,71.53 27.81,72.61 C32.2 | C31.2 29.2,56.48 26.79,56.48 26.79,71.46 26.73,71.53 | v29.46,50 29.2,50.13 29.2,55.97 C31.2 | v30.98,61.56 30.98,57.37 30.47,56.86 C31.2 | 69.72,71.84 69.46,72.35 69.46,72.73 V2.2 68.96,74.26 68.96,77.18 V1.2 68.96,78.7 68.96,82.26 C9.- 69.46,83.78 69.46,85.18 74.8,85.18 IC1.GND 75.05,86.19 74.16,87.08 74.16,92.93 PAD2.B3,3 | 69.72,71.84 75.05,71.84 SV1.3 | 69.72,71.84 69.59,69.81 C3.- 70.1,68.29 73.78,64.73 73.78,60.92 75.05,59.52 IC2.GND | v53.72,90.64 53.72,90.13 53.21,89.62 C15.2 | 61.91,41.94 62.99,40.73 62.99,36.66 63.75,35.9 IC11.1 67.56,33.49 67.56,25.74 69.46,22.95 X1.5 70.1,21.55 74.04,17.61 74.04,7.07 PAD3.B3,3 | 61.91,41.94 60.83,43.02 C27.2 | 61.91,41.94 v61.84,42 | SJ8.2 49.02,11.9 50.03,11.9 SJ7.2 51.18,11.9 51.18,5.04 50.41,4.28 SV2.5 | IC7.42 55.11,27.65 55.62,26.63 55.62,18.38 57.27,16.98 SJ6.1 58.67,16.22 58.67,10.5 C30.2 59.05,9.23 59.05,5.04 59.43,4.53 | IC6.1 IC6.2 | v4.06,18.38 4.06,17.61 C33.2 2.66,15.08 2.66,12.15 3.55,11.65 C24.2 | T1.1 6.85,11.9 4.82,11.9 4.82,11.65 C24.2 | C24.2 3.55,10.63 3.55,7.07 PAD4.B3,3 | IC6.31 4.06,33.49 4.95,32.73 4.95,30.57 4.19,29.93 4.19,22.82 5.08,21.93 SV6.9 | 31.81,25.43 31.24,24.85 29.33,24.85 JP1.1 | 31.81,25.43 31.87,25.36 | SV5.1 32.89,7.33 32.89,11.77 SL1.1 33.02,23.96 31.81,25.43
  Top 0.254: 40.51,29.68 40.51,24.47 IC7.30 | 40.51,29.68 40.51,32.98 38.6,32.98 IC7.22 | v48,30.95 48,38.7 IC7.10 | v41.14,29.68 40.51,29.68 | v70.35,46.7 70.35,55.97 69.46,56.86 C29.- | v33.02,28.79 33.02,33.24 33.4,33.62 33.4,34.38 33.27,34.51 33.27,53.17 30.47,55.97 C31.2 | v61.59,47.33 61.59,45.43 62.48,44.54 C12.2
  Bottom 0.254: IC3.4 8.38,78.96 12.57,78.96 12.57,82 5.58,82 5.58,85.18 4.44,87.72 PAD1.B3,3 | SV4.4 15.11,96.38 | v10.66,84.8 10.79,84.8 11.43,85.43 IC5.7 | C19.2 43.81,62.06 43.3,62.57 v39.49,62.57 39.11,62.32 38.35,61.56 v30.98,61.56 | v29.46,50 IC8.10 | C41.1 66.8,83.53 67.05,83.27 68.45,83.27 C9.- | C39.1 67.3,57.37 68.45,57.37 C29.- 69.97,57.87 74.16,57.87 74.8,58.51 IC2.GND | C38.1 68.07,68.8 69.08,68.8 C3.- | 48.45,95.02 49.14,95.72 SV7.2 | 48.45,95.02 47.49,94.07 IC13.2 | 48.45,95.02 48.51,94.96 48.64,94.96 49.53,94.07 IC13.4 50.03,94.07 50.54,94.83 54.22,94.83 | v53.72,90.64 54.61,92.04 IC13.8 | IC13.8 55.11,92.04 55.88,92.04 IC13.9 56.38,92.04 57.15,92.04 IC13.10 57.65,94.07 59.69,96.1 62.73,96.1 C4.- 64.26,96.1 65.65,96.1 65.91,95.85 C40.1 67.43,94.83 72.13,94.83 PAD2.B3,3 | 54.22,94.83 54.73,94.07 54.61,94.07 IC13.8 | 54.22,94.83 54.22,95.72 SV7.4 | 61.84,42.89 64.13,42.89 64.51,42.38 IC10.10 64.64,41.11 64.64,42.51 v70.35,46.7 | 61.84,42.89 58.8,42.89 58.41,41.11 IC10.15 | v61.84,42 61.84,42.89 | 60.07,1.74 62.61,3.9 63.24,4.53 C18.2 64.38,4.53 65.4,2.63 72,2.63 72.89,2.88 PAD3.B3,3 | 58.54,1.23 51.56,1.23 50.8,2.12 SV2.5 | C17.2 9.39,34.63 9.39,32.98 C28.2 10.28,32.09 14.35,32.09 14.85,31.58 IC6.1 22.47,31.58 25.27,28.92 33.02,28.92 v33.02,28.79 34.54,28.03 40.51,28.03 41.02,28.54 41.14,29.3 v41.14,29.68 43.68,29.68 43.94,30.06 45.72,30.06 C16.2 46.73,30.57 47.11,30.95 v48,30.95 59.3,30.95 C42.1 60.83,30.95 63.75,30.95 C43.1 65.27,30.95 66.8,29.43 71.11,29.43 71.11,23.84 70.23,22.95 X1.5 | IC8.1 21.97,38.32 21.33,37.94 11.55,37.94 9.52,35.65 C17.2
  Bottom 0.254: IC6.31 4.44,34.38 4.69,34.63 7.87,34.63 C17.2 | v4.06,18.38 5.33,18.76 SV6.9 5.33,17.49 5.46,17.36 13.71,17.36 13.71,19.65 SV6.1 | SV5.8 25.9,4.53 27.05,5.68 31.49,5.68 32.25,6.44 SV5.1 | 58.16,47.33 v61.59,47.33
  Bottom 0.61: 58.16,47.84 58.16,47.33
  pour Bottom (isolate 0.406): -0.64,99.53 -0.64,0.47 79.37,0.47 79.37,99.53 41.27,99.53 41.27,91.91 40,91.91 40,90.64 41.27,90.64 41.27,85.56 28.57,85.56 28.57,99.53
  pour Top (isolate 0.406): -0.64,99.53 -0.64,0.47 78.1,0.47 78.1,99.53 42.54,99.53 42.54,91.91 40,91.91 40,90.64 42.54,90.64 42.54,85.56 28.57,85.56 28.57,99.53
GNDA
  Top 0.254: SV3.3 36.19,94.45 C5.2 34.79,94.45 30.86,94.45 | 30.86,94.45 30.86,91.4 IC12.4 | 30.86,94.45 30.86,95.59 SV3.1
  Bottom 0.254: C1.2 35.81,94.58 35.81,95.59 SV3.3 | C2.1 30.73,94.58 30.73,95.59 SV3.1 | C6.2 38.1,87.85 31.87,87.85 C7.1 30.86,88.86 30.86,89.88 IC12.4
  pour Bottom (isolate 0.305): 29.84,98.77 29.84,86.96 40.25,86.96 40.25,86.83 40.25,99.53 29.84,99.53
  pour Top (isolate 0.305): 29.97,99.66 29.97,87.34 40.38,87.34 40.38,99.66
INT0-  (via drill 0.61)
  Top 0.254: v45.97,57.37 43.05,60.29 43.05,69.56 IC9.14 43.05,72.1 43.43,72.61 46.22,72.61 46.22,76.67 47.75,77.69 RN1.4 | IC7.8 v50.8,52.54
  Bottom 0.254: v50.8,52.54 v45.97,57.37
IO0  (via drill 0.61)
  Top 0.254: v38.86,15.33 39.49,16.98 39.49,20.15 41.02,21.68 41.65,22.44 IC7.31 | v32,8.85 31.62,8.09 31.62,6.18 30.73,4.79 SV5.4
  Bottom 0.254: v32,8.85 v38.86,15.33
IO1  (via drill 0.61)
  Top 0.254: v38.35,19.77 38.35,21.55 39.11,22.44 IC7.29 | v29.08,19.39 29.08,8.47 27.81,7.46 SV5.5
  Bottom 0.254: v38.35,19.77 37.33,19.39 v29.08,19.39
IO2  (via drill 0.61)
  Top 0.254: v37.08,15.2 37.33,15.46 37.33,24.98 IC7.28 | v31.36,10.38 29.08,7.2 29.08,5.8 28.19,4.79 SV5.6
  Bottom 0.254: v37.08,15.2 37.08,14.57 33.52,11.14 v31.36,10.38
IO3  (via drill 0.61)
  Top 0.254: v39.49,26.25 38.6,26.25 IC7.27 | v31.74,23.46 26.54,21.42 26.54,8.22 25.65,7.33 SV5.7
  Bottom 0.254: v39.49,26.25 36.7,23.46 v31.74,23.46
IO4  (via drill 0.61)
  Top 0.254: v43.3,37.17 43.3,38.7 IC7.14 | v29.2,36.41 29.08,35.14 29.08,30.57 24,25.49 24,6.44 23.24,5.55 20.44,5.55 20.44,6.06 SV5.11
  Bottom 0.254: v43.3,37.17 42.92,37.55 36.32,37.55 35.68,36.54 33.14,36.54 32.63,37.05 30.98,37.05 v29.2,36.41
IO5  (via drill 0.61)
  Top 0.254: v40,41.49 40,41.11 40.38,40.73 IC7.16 | v37.59,41.49 34.79,37.17 34.79,32.47 34.41,32.09 34.41,26.12 34.16,25.87 34.16,24.22 34.41,23.96 34.41,6.57 33.02,5.3 32.25,5.3 31.74,4.92 31.49,4.15 31.49,3.52 30.86,3.14 22.98,3.14 22.98,3.52 SV5.10 22.09,3.9 20.82,3.9 SV5.12
  Bottom 0.254: v37.59,41.49 v40,41.49
IO6  (via drill 0.61)
  Top 0.254: v53.08,19.27 57.65,14.31 57.65,8.09 RN3.2 | v49.53,19.27 49.53,20.03 49.27,20.28 49.27,22.19 49.53,22.44 IC7.37
  Bottom 0.254: SL1.5 22.6,11.77 22.47,11.77 18.03,7.33 SV5.13 17.9,6.06 18.92,4.92 18.92,3.01 36.32,3.01 37.84,4.66 47.62,4.66 48.89,4.92 56.51,4.92 56.64,5.04 RN3.2 | v49.53,19.27 v53.08,19.27 53.34,19.27
IO7  (via drill 0.61)
  Top 0.254: IC7.24 36.57,30.06 36.06,29.55 36.06,21.04 v36.44,20.41 v36.44,16.47 | v22.09,20.66 22.09,17.23 20.31,16.34 SL1.6 20.06,11.77 19.04,10.76 19.04,5.8 18.03,4.79 SV5.14 | v54.99,15.46 54.99,8.09 RN3.3
  Bottom 0.254: v22.09,20.66 v36.44,20.41 | v36.44,16.47 40,16.47 40.13,16.6 49.02,16.6 49.14,16.73 53.72,16.73 v54.99,15.46
LED  (via drill 0.61)
  Top 0.254: C24.1 4.82,13.42 4.82,13.81 6.85,13.81 T1.2 7.62,14.19 9.39,14.19 9.39,18.5 v9.14,18.25 | v9.14,25.11 9.65,26.63 9.52,52.67 9.01,53.68 v9.01,69.18 | v48.89,72.99 48.89,72.1 IC9.9 | v57.53,74.77 57.53,78.07 58.8,79.34 RN2.9
  Bottom 0.254: v9.14,18.25 v9.14,25.11 | v9.01,69.18 14.35,72.35 48,72.35 v48.89,72.99 48.89,73.11 50.16,74.38 57.15,74.38 v57.53,74.77
LOCK  (via drill 0.61)
  Top 0.254: v22.47,74.26 22.47,85.81 R6.1 | v51.68,75.65 IC9.7
  Bottom 0.254: v22.47,74.26 40.76,74.26 42.16,75.65 v51.68,75.65 52.45,75.65 52.95,76.16 58.03,76.16 58.67,75.27 RN2.7
MCISP  (via drill 0.61)
  Top 0.254: JP1.2 29.33,26.89 R13.1 31.36,27.77 31.36,33.36 v32.38,34 | v35.68,34.38 35.68,35.52 36.57,36.41 IC7.19
  Bottom 0.254: v35.68,34.38 35.3,34 v32.38,34
N$1
  Bottom 0.406: C8.1 54.45,52 | 54.48,52.03 58.16,52.03 IC10.2
  Bottom 0.61: 54.45,52 54.48,52.03
N$3  (via drill 0.61)
  Top 0.254: v11.3,80.48 12.06,80.48 C34.1
  Bottom 0.254: v11.3,80.48 7.62,80.48 7.11,79.97 IC3.3
N$4  (via drill 0.61)
  Top 0.254: v4.57,80.86 4.57,81.24 4.95,81.62 C10.2
  Bottom 0.254: v4.57,80.86 4.57,79.97 IC3.1
N$5
  Bottom 0.254: 64.26,71.46 64.38,71.46
  Bottom 1.016: 64.38,71.46 66.03,73.11 V2.3 | D2.A 64.26,71.46
N$6
  Top 0.254: R4.1 40.51,93.18 38.86,93.18 C5.1 38.48,93.05 38.48,91.4 IC12.1
N$7  (via drill 0.61)
  Top 0.254: v64.13,52.16 65.91,48.98 65.91,47.08 C13.2
  Bottom 0.254: v64.13,52.16 62.73,52.16 62.23,51.65 62.23,50.89 IC10.5
N$8  (via drill 0.61)
  Top 0.254: v62.48,48.22 62.99,47.33 C13.1
  Bottom 0.254: v62.48,48.22 62.61,48.48 61.46,48.48 60.96,48.98 IC10.4
N$9  (via drill 0.61)
  Top 0.254: v60.32,48.22 60.32,47.08 C26.2
  Bottom 0.254: v60.32,48.22 59.56,48.98 IC10.3
N$10  (via drill 0.61)
  Top 0.254: v56.76,48.22 56.76,47.08 C26.1
  Bottom 0.254: v56.76,48.22 56.76,48.98 IC10.1
N$11  (via drill 0.61)
  Top 0.254: v65.02,48.22 65.02,45.05 65.53,44.54 C12.1
  Bottom 0.254: v65.02,48.22 63.62,48.22 63.5,48.98 IC10.6
N$13
  Bottom 1.016: V1.3 65.91,77.69 64.77,76.54 63.62,76.54 D1.A
N$17
  Bottom 0.254: R15.1 38.35,94.58 38.35,95.59 SV3.4
N$18
  Bottom 0.254: IC12.2 35.94,91.4 35.94,91.78 C1.1 36.83,91.78 38.1,91.78 R15.2
N$19  (via drill 0.6)
  Top 0.254: v27.65,90.26 R2.1
  Bottom 0.254: v27.65,90.26 27.7,89.71 27.73,86.31 27.73,85.77 31.87,85.81 C7.2 30.86,84.8 30.86,83.78 IC12.5
N$20
  Bottom 0.254: C2.2 31.74,91.78 33.02,91.78 R16.2 33.4,91.78 33.4,91.4 IC12.3
N$21
  Bottom 0.254: R16.1 33.27,94.58 33.27,95.59 SV3.2
N$22
  Top 0.254: R10.1 28.46,88.67 30.22,85.05 34.54,85.05 35.55,84.29 37.97,84.29 38.48,83.78 IC12.8
  Bottom 0.254: C6.1 39.49,85.81 39.87,85.81 40.51,84.92 40.51,83.66 39.37,83.02 IC12.8
N$23
  Top 0.254: IC12.7 37.33,81.62 R9.1
N$24
  Top 0.254: IC12.6 33.27,81.5 29.08,81.5 29.08,82.89 28.95,83.02 R8.1
N$25
  Top 0.254: R7.1 65.65,11.9 64.77,11.52 64.77,5.42 R1.3
N$30
  Top 0.254: SJ2.2 39.11,13.55 38.73,13.17 37.97,12.66 SJ1.1 36.44,11.77 36.44,7.96 34.67,4.66 34.54,4.53 33.27,4.53 SV5.2
N$31  (via drill 0.61)
  Top 0.254: v8.38,15.84 7.11,15.71 C33.1 | v21.58,15.46 21.58,15.33 21.58,7.96 22.35,7.33 SV5.9
  Bottom 0.254: v8.38,15.84 10.92,15.84 11.3,15.46 v21.58,15.46
N$32  (via drill 0.61)
  Top 0.254: SJ6.2 SJ3.2 61.34,18.12 61.84,18.12 v61.84,14.44
  Bottom 0.254: v61.84,14.44 66.03,10.25 R1.1
N$33
  Top 0.254: R7.2 63.5,13.81 63.5,16.22 SJ5.1 64,16.22 65.02,16.22 SJ4.1
PLLCLK  (via drill 0.61)
  Top 0.254: v16.76,82.26 16.76,78.45 19.93,78.45 19.93,73.11 v20.44,71.21 | v52.83,71.84 52.83,69.3 IC9.6
  Bottom 0.254: v20.44,71.21 22.09,71.84 v52.83,71.84 58.67,71.84 RN2.6 | v16.76,82.26 IC5.3
PLLDATA  (via drill 0.61)
  Top 0.254: v20.57,85.69 20.57,73.11 21.33,71.84 v23.87,69.94 | v55.24,69.94 55.24,68.54 54.73,68.03 IC9.5
  Bottom 0.254: v20.57,85.69 19.55,85.69 IC5.1 | v23.87,69.94 v55.24,69.94 58.41,69.94 RN2.5
PLLLE  (via drill 0.61)
  Top 0.254: v25.01,81.24 25.01,80.1 26.41,78.7 32.76,71.97 v32.76,69.05 | v51.43,67.65 51.43,67.53 52.19,66.76 IC9.4
  Bottom 0.254: v25.01,81.24 24.76,81.24 24.63,81.11 16,81.11 14.47,85.43 IC5.5 | v32.76,69.05 34.16,67.65 v51.43,67.65 58.54,67.65 RN2.4
PLLLOCK  (via drill 0.6)
  Top 0.254: R6.2 22.44,89.28 v22.22,89.5
  Bottom 0.254: v22.22,89.5 22.22,89.62 22.09,89.75 15.74,89.75 14.22,91.28 IC5.10
PSEN-  (via drill 0.61)
  Top 0.254: v41.52,47.84 41.52,44.41 38.6,41.62 38.6,38.19 IC7.18 | v42.79,49.11 IC9.32
  Bottom 0.254: v41.52,47.84 v42.79,49.11
RD-  (via drill 0.61)
  Top 0.254: v41.65,56.6 40.38,57.87 40.38,65.62 38.48,67.53 IC9.19 | v49.53,52.54 IC7.9 | v33.27,55.71 33.27,67.91 33.65,68.29 33.65,76.67 34.79,77.81 RN1.9
  Bottom 0.254: v49.53,52.54 45.84,56.22 42.03,56.22 v41.65,56.6 41.27,56.35 40.64,55.71 v33.27,55.71 16.12,55.71 14.22,53.81 12.31,52.16 4.44,52.16 IC6.24
RES0  (via drill 0.61)
  Top 0.254: IC9.8 v50.41,72.99
  Bottom 0.254: v50.41,72.99 51.81,73.62 60.83,73.62 61.46,74.38 61.46,76.8 60.57,76.8 RN2.8
RESET  (via drill 0.6, 0.61)
  Top 0.254: IC9.10 47.62,72.1 v47.62,74.77 47.62,74.89 | R3.1 18.16,74.52 v18.16,73.24
  Bottom 0.254: 13.33,73.24 11.81,74.77 6.98,74.77 IC3.6 | 13.33,73.24 40.89,73.24 42.41,74.77 v47.62,74.77 | 13.33,73.24 v18.16,73.24
RESET-  (via drill 0.61)
  Top 0.254: v48,43.14 48,41.49 47.24,40.73 IC7.11 | v73.02,53.81 73.02,57.37 72.51,57.87 72.51,64.1 67.94,68.41 v67.94,79.59
  Bottom 0.254: 51.49,77.5 52.19,78.19 RN1.2 | 51.49,77.5 50.29,76.29 41.4,76.29 40.13,75.02 24,75.02 23.24,75.4 21.2,75.4 19.93,74.89 14.22,74.89 12.57,76.54 6.34,76.54 6.34,71.84 6.6,71.59 7.62,71.59 8.12,72.1 IC3.5 | v48,43.14 48,43.4 48.89,44.03 54.73,44.03 65.65,46.44 v73.02,53.81 | v67.94,79.59 67.56,79.21 62.1,79.34 61.21,78.7 56.89,78.7 56,77.05 51.56,77.05 51.49,77.5
RS232IN  (via drill 0.61)
  Top 0.254: v64.13,37.43 64,37.55 64,49.11 v61.84,53.17 | v49.27,60.54 46.48,68.16 46.48,69.56 IC9.11
  Bottom 0.254: v64.13,37.43 64,37.43 62.23,39.2 IC10.12 | v61.84,53.17 57.27,55.84 54.35,55.84 49.65,60.54 v49.27,60.54
RS232OUT  (via drill 0.61)
  Top 0.254: v66.92,38.32 66.92,53.81 66.29,54.45 65.02,57.62 65.02,61.43 v63.11,64.99 | v45.97,66.26 44.32,67.91 44.32,69.56 IC9.13
  Bottom 0.254: v66.92,38.32 64.38,38.32 63.5,39.2 IC10.11 | v63.11,64.99 62.23,65.88 57.02,65.88 56.64,66.26 v45.97,66.26
SEL0  (via drill 0.61)
  Top 0.254: SJ8.1 47.49,13.68 45.08,13.68 R11.1 44.45,14.44 45.33,15.33 v45.33,21.42 | v40,35.14 38.6,35.14 IC7.20 | v45.97,35.14 45.97,26.12 v45.08,25.36
  Bottom 0.254: v45.97,35.14 v40,35.14 | v45.33,21.42 45.21,21.68 45.08,21.81 v45.08,25.36
SEL1  (via drill 0.61)
  Top 0.254: 51.81,14.31 51.3,14.31 51.18,13.55 SJ7.1 51.81,14.31 | 51.81,14.31 53.21,14.31 53.26,14.36 R12.1 | v42.54,26.38 42.54,29.17 41.4,31.2 41.02,33.87 38.6,33.87 IC7.21 | 51.81,14.31 53.46,14.31 53.46,17.61 51.81,17.61 v51.81,21.3
  Bottom 0.254: v42.54,26.38 48,26.38 48.64,25.62 51.81,22.19 v51.81,21.3
TAST0  (via drill 0.61)
  Top 0.254: v47.87,20.41 48.26,22.06 IC7.36 | v40.64,15.33 v40.64,19.65 | SV2.1 39.75,4.28 39.75,5.55 RN3.9
  Bottom 0.254: v47.87,20.41 47.87,20.03 47.75,19.9 43.3,19.9 42.79,20.41 41.52,20.41 v40.64,19.65 | v40.64,15.33 40.64,8.09 40.25,8.09 RN3.9
TAST1  (via drill 0.61)
  Top 0.254: v51.94,28.16 51.94,30.44 52.83,31.33 IC7.1 | v42.03,19.39 42.92,17.49 v42.92,12.41 | SV2.2 42.29,4.28 42.29,5.55 RN3.8
  Bottom 0.254: v51.94,28.16 51.94,23.08 52.83,22.19 52.83,20.28 49.02,20.28 48.13,19.14 42.41,19.14 42.16,19.39 v42.03,19.39 | v42.92,12.41 42.67,8.09 RN3.8
TAST2  (via drill 0.61)
  Top 0.254: v57.65,20.54 57.65,27.14 57.53,27.39 56.26,29.17 55.37,30.19 IC7.44 | SV2.3 44.83,4.28 44.83,5.55 RN3.7
  Bottom 0.254: v57.65,20.54 57.91,20.54 58.41,19.14 58.41,9.23 46.73,9.23 45.59,7.84 RN3.7
TAST3  (via drill 0.61)
  Top 0.254: v56.64,19.65 56.64,26.89 55.11,29.04 IC7.43 | v45.33,10 RN3.6 47.37,5.55 47.37,4.28 SV2.4
  Bottom 0.254: v56.64,19.65 56.64,19.39 57.65,18.12 57.65,10 v45.33,10
TCK  (via drill 0.61)
  Top 0.254: v42.41,21.55 42.92,22.44 IC7.32 | v17.39,20.79 15.87,23.33 SV6.2 15.36,24.22 15.36,24.98 13.46,26.89 RN4.2
  Bottom 0.254: v42.41,21.55 18.41,21.55 v17.39,20.79
TDI  (via drill 0.61)
  Top 0.254: v50.8,37.68 51.81,38.7 IC7.7 | v24.25,36.54 24.25,32.98 v21.58,29.55 | SV6.10 5.58,24.47 5.58,26.5 RN4.5
  Bottom 0.254: v50.8,37.68 50.41,38.19 34.92,38.19 34.41,37.55 25.14,37.55 v24.25,36.54 | v21.58,29.55 7.11,29.55 RN4.5
TDO  (via drill 0.61)
  Top 0.254: v50.41,21.55 50.41,22.31 50.54,22.44 IC7.38 | RN4.3 11.17,26.5 11.3,26.38 11.3,24.73 12.31,23.71 SV6.4
  Bottom 0.254: v50.41,21.55 46.86,21.55 46.48,20.54 43.56,20.54 43.3,22.44 18.41,22.44 16.38,25.11 14.6,25.11 13.2,24.6 SV6.4
TMS  (via drill 0.61)
  Top 0.254: v45.08,28.79 45.08,31.08 44.7,31.46 44.7,38.7 IC7.13
  Bottom 0.254: v45.08,28.79 44.19,28.66 43.68,28.16 42.16,27.39 32.25,27.27 29.33,23.33 19.55,23.33 17.01,25.74 16.57,25.81 10.35,25.81 | 10.35,25.81 10.28,24.47 SV6.6 | RN4.4 8.38,26.89 10.35,25.81
V24IN
  Bottom 0.254: IC10.13 60.96,39.2 63.62,36.03 66.03,36.03 69.21,30.44 X1.2
V24OUT  (via drill 0.61)
  Top 0.254: v59.94,38.32 63.24,35.14 63.5,33.11 66.29,30.57 v66.29,28.16
  Bottom 0.254: v59.94,38.32 59.69,38.32 59.69,39.2 IC10.14 | 66.16,28.16 v66.29,28.16 69.21,28.16 X1.3
VLCD
  Bottom 0.254: R1.2 68.19,7.84 64.77,7.84 C18.1 63.24,8.6 47.11,8.6 46.35,7.46 46.35,5.17 36.06,5.17 33.4,7.84 29.97,7.84 | 29.97,7.84 29.97,10.63 29.33,11.39 28.57,12.15 SL1.3 | 29.97,7.84 29.97,7.33 SV5.3
VREF
  Top 0.406: R2.2 28.39,94.13 28.93,94.67 28.93,96.37 27.5,97.8 VREF1.MP
WR-  (via drill 0.61)
  Top 0.254: v45.46,42.63 45.46,40.73 IC7.12 | v38.98,49.11 35.05,53.17 35.05,56.48 v35.17,57.24 | v42.92,57.11 41.52,59.02 41.52,66.26 38.48,68.8 IC9.18 | v35.94,70.83 35.94,69.3 IC9.18 | RN1.8 37.33,77.81 37.33,69.3 IC9.18
  Bottom 0.254: v38.98,49.11 v45.46,42.63 | v35.17,57.24 35.43,57.49 42.54,57.49 v42.92,57.11 | v35.94,70.83 23.11,70.83 20.06,68.41 16.89,68.41 14.98,65.88 1.39,65.88 1.39,40.73 2.28,39.84 IC6.29
XA
  Bottom 0.254: 74.8,77.69 74.92,77.56
  Bottom 1.016: 74.8,77.69 72.51,77.69 V1.1 | 74.92,77.56 SV1.5
XB
  Bottom 0.254: 72.13,72.73 72,72.73
  Bottom 1.016: 72.13,72.73 74.92,69.94 SV1.2 | 72,72.73 V2.1
XCLK  (via drill 0.61)
  Top 0.254: v25.68,90.53 25.78,90.64 R10.2
  Bottom 0.254: v25.68,90.53 25.01,90.39 18.16,90.39 17.01,91.66 IC5.12
XCS-  (via drill 0.61)
  Top 0.254: v28.32,79.72 28.32,81.75 25.78,84.29 R8.2
  Bottom 0.254: v28.32,79.72 28.06,79.72 26.54,80.35 15.49,80.35 14.6,82.51 13.84,83.27 9.77,83.27 9.77,89.88 11.43,91.66 IC5.8
XD
  Top 0.254: 63.11,87.21 63.24,87.34
  Top 1.016: 63.24,87.34 63.24,90.51 C4.+ | D1.C 63.11,87.21
  Bottom 0.254: 65.91,91.78 C40.2 | C4.+ 64.26,91.53
  Bottom 1.016: 65.91,91.78 65.65,91.53 64.26,91.53 | IC1.IN 74.8,88.48 71.5,91.78 67.43,91.78 C40.2
XF
  Bottom 0.254: 68.96,64.22 69.08,64.22 | 68.07,65.11 C38.2 67.05,65.11
  Bottom 1.016: 68.07,65.11 68.96,64.22 | 69.08,64.22 C3.+ 70.61,63.72 72.89,63.72 74.8,61.81 IC2.IN | 67.05,65.11 63.75,61.81 D2.C
XLED  (via drill 0.61)
  Top 0.254: v10.16,10.88 9.65,11.39 9.65,12.92 T1.3
  Bottom 0.254: v10.16,10.88 14.98,6.95 SV5.15 15.74,7.07 16.5,7.84 17.52,8.6 17.52,11.77 SL1.7
XPLLCLK  (via drill 0.61)
  Top 0.254: v15.74,88.23 18.16,88.23 v18.92,88.86 | v23.49,89.12 23.49,93.56 20.3,94.3 SV4.2
  Bottom 0.254: v15.74,88.23 15.74,87.34 IC5.4 | v18.92,88.86 19.3,88.86 20.06,88.1 22.86,88.1 23.11,88.35 v23.49,89.12
XPLLDATA  (via drill 0.61)
  Top 0.254: v24,86.32 24.38,88.35 24.38,95.59 SV4.1
  Bottom 0.254: v24,86.32 22.98,84.42 19.04,84.42 18.03,85.05 IC5.2
XPLLLE  (via drill 0.6, 0.61)
  Top 0.254: v11.81,90.26 11.79,92.58 11.82,94.48 11.94,94.57 v16.5,94.58
  Bottom 0.254: v16.5,94.58 17.64,95.85 SV4.3 | IC5.6 v11.81,90.26
XPLLLOCK
  Bottom 0.254: IC5.11 15.49,93.94 15.36,94.07 12.57,94.07 12.57,96.48 SV4.5
XTAL1  (via drill 0.61)
  Top 0.254: C31.1 29.2,58.76 28.7,59.27 28.7,61.56 Q1.2 | v35.05,62.57 35.05,64.1 35.94,64.99 IC9.21
  Bottom 0.254: v35.05,62.57 28.95,62.57 Q1.2
XTAL2  (via drill 0.61)
  Top 0.254: C32.1 28.19,70.7 28.19,67.91 Q1.1 | v35.05,66.76 35.94,66.76 IC9.20
  Bottom 0.254: v35.05,66.76 34.79,67.02 29.08,67.02 Q1.1

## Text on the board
Bottom: DL5MEA/DK7NT | AA 2005 - V1.1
